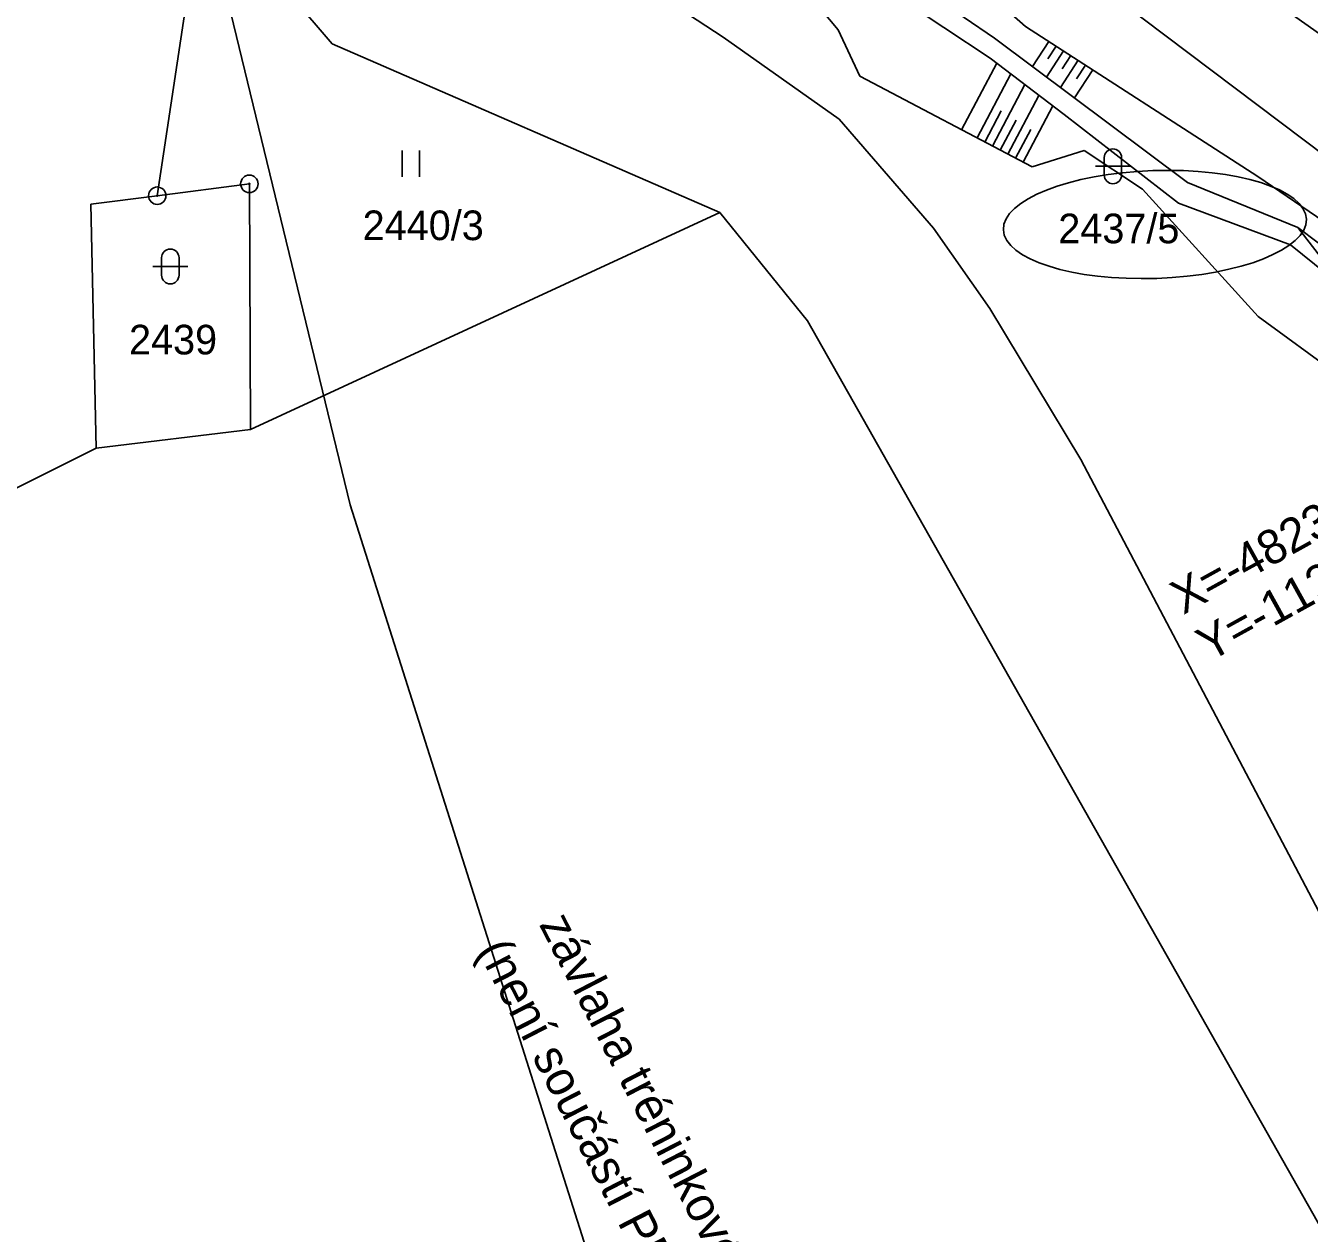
# Model space of a CAD drawing. Extents: x -483721 to -481876, y -1129170 to -1127366.
# Drawn here: x -482470.6 to -482396.9, y -1128316.3 to -1128247 of the extents above; entities that cross this region are included whole.
import ezdxf

# ---------------------------------------------------------------- set-up
doc = ezdxf.new("R2010")
doc.units = 0
for name, color, linetype in [('Hranice parcel', 7, 'Continuous'), ('kresba', 7, 'Continuous'), ('oblast', 7, 'Continuous'), ('Parcelní čísla', 7, 'Continuous'), ('SO 01', 7, 'Continuous'), ('u_návrh_popis', 7, 'Continuous'), ('u_OP_lesa', 7, 'Continuous'), ('u_vytyčení', 7, 'Continuous'), ('Značky bodu BP', 7, 'Continuous'), ('Značky kultur', 7, 'Continuous'), ('ˇ12', 7, 'Continuous')]:
    doc.layers.add(name, color=color, linetype=linetype)

msp = doc.modelspace()

# ---------------------------------------------------------------- linework, layer by layer
at = {"layer": 'Hranice parcel'}
for p, q in [((-482463, -1128256.76), (-482460.37, -1128239.37)), ((-482460.37, -1128239.37), (-482452.95, -1128248.05)), ((-482443.21, -1128239.32), (-482430.5, -1128247.66)), ((-482452.95, -1128248.05), (-482430.69, -1128257.73)), ((-482457.71, -1128256.08), (-482463, -1128256.76)), ((-482457.64, -1128270.17), (-482457.71, -1128256.08)), ((-482463, -1128256.76), (-482466.82, -1128257.25)), ((-482466.82, -1128257.25), (-482466.51, -1128271.25)), ((-482430.69, -1128257.73), (-482457.64, -1128270.17)), ((-482457.64, -1128270.17), (-482466.51, -1128271.25)), ((-482466.51, -1128271.25), (-482500.1, -1128287.99)), ((-482409.98, -1128271.91), (-482389.07, -1128311.59))]:
    msp.add_line(p, q, dxfattribs=at)
for points in [[(-482378.58, -1128267.55), (-482422.4, -1128234.54), (-482424.97, -1128232.6), (-482436.98, -1128222.89), (-482441.06, -1128219.38), (-482451.1, -1128211.21), (-482453.27, -1128206.98), (-482457.35, -1128200.28), (-482472.77, -1128174.94)], [(-482430.5, -1128247.66), (-482423.85, -1128252.37), (-482418.43, -1128258.62), (-482415.19, -1128263.23), (-482409.98, -1128271.91)], [(-482389.1, -1128328.49), (-482425.67, -1128263.94), (-482430.69, -1128257.73)]]:
    msp.add_lwpolyline(points, dxfattribs=at)
at = {"layer": 'kresba'}
msp.add_line((-482390.19, -1128268.135), (-482397.51, -1128258.578), dxfattribs=at)
at = {"layer": 'oblast'}
msp.add_ellipse((-482405.72, -1128258.412), major_axis=(-8.7, -0.304), ratio=0.355414, dxfattribs=at)
at = {"layer": 'SO 01'}
msp.add_lwpolyline([(-482368.023, -1128257.275), (-482390.756, -1128251.361), (-482390.756, -1128251.361), (-482399.122, -1128245.437)], dxfattribs=at)
at = {"layer": 'u_OP_lesa'}
msp.add_lwpolyline([(-482417.647, -1128382.401), (-482432.277, -1128336.352), (-482451.921, -1128274.508), (-482459.735, -1128242.317), (-482439.858, -1128216.048), (-482430.661, -1128194.677), (-482468.003, -1128132.413)], dxfattribs=at)
at = {"layer": 'Značky bodu BP'}
for centre, radius in [((-482457.71, -1128256.08), 0.5), ((-482463, -1128256.76), 0.5), ((-482457.71, -1128256.08), 0.0303), ((-482463, -1128256.76), 0.0303)]:
    msp.add_circle(centre, radius, dxfattribs=at)
at = {"layer": 'Značky kultur'}
for p, q in [((-482448.941, -1128255.67), (-482448.941, -1128254.17)), ((-482447.94, -1128255.67), (-482447.94, -1128254.17)), ((-482408.631, -1128254.571), (-482408.631, -1128255.572)), ((-482407.629, -1128255.572), (-482407.629, -1128254.571)), ((-482409.131, -1128255.071), (-482407.129, -1128255.071)), ((-482463.251, -1128260.821), (-482461.249, -1128260.821)), ((-482462.751, -1128260.321), (-482462.751, -1128261.322)), ((-482461.749, -1128261.322), (-482461.749, -1128260.321))]:
    msp.add_line(p, q, dxfattribs=at)
for centre, start, end in [((-482408.13, -1128254.571), 0, 180), ((-482408.13, -1128255.571), 180, 359.98789), ((-482462.25, -1128260.321), 0, 180), ((-482462.25, -1128261.321), 180, 359.98789)]:
    msp.add_arc(centre, 0.5, start, end, dxfattribs=at)
at = {"layer": 'ˇ12'}
for p, q in [((-482423.9, -1128247.24), (-482426.72, -1128243.88)), ((-482420.57, -1128243.86), (-482414.92, -1128247.72)), ((-482415.17, -1128248.87), (-482421.67, -1128244.55)), ((-482416.51, -1128244.08), (-482413.14, -1128247.04)), ((-482422.66, -1128249.89), (-482423.9, -1128247.24)), ((-482413.14, -1128247.04), (-482399.8, -1128255.66)), ((-482414.92, -1128247.72), (-482403.85, -1128256)), ((-482411.8, -1128247.9), (-482412.74, -1128249.35)), ((-482411.38, -1128248.17), (-482411.86, -1128248.91)), ((-482416.82, -1128252.97), (-482414.8, -1128249.15)), ((-482415.17, -1128248.87), (-482410.93, -1128252.1)), ((-482410.96, -1128248.45), (-482411.94, -1128249.95)), ((-482410.12, -1128248.99), (-482411.13, -1128250.55)), ((-482410.54, -1128248.72), (-482411.04, -1128249.48)), ((-482412.76, -1128255.11), (-482422.66, -1128249.89)), ((-482415.93, -1128253.44), (-482413.99, -1128249.77)), ((-482409.28, -1128249.53), (-482410.33, -1128251.15)), ((-482409.7, -1128249.26), (-482410.22, -1128250.06)), ((-482415.04, -1128253.91), (-482413.18, -1128250.38)), ((-482414.16, -1128254.38), (-482412.38, -1128251)), ((-482415.49, -1128253.68), (-482414.54, -1128251.88)), ((-482413.28, -1128254.84), (-482411.57, -1128251.61)), ((-482410.93, -1128252.1), (-482404.37, -1128257.19)), ((-482414.6, -1128254.14), (-482413.69, -1128252.42)), ((-482413.72, -1128254.61), (-482412.85, -1128252.96)), ((-482409.78, -1128254.16), (-482412.76, -1128255.11)), ((-482409.78, -1128254.16), (-482406.43, -1128256.39)), ((-482399.8, -1128255.66), (-482389.79, -1128262.5)), ((-482406.43, -1128256.39), (-482399.79, -1128263.7)), ((-482403.85, -1128256), (-482397.51, -1128258.58)), ((-482404.37, -1128257.19), (-482397.94, -1128259.58)), ((-482397.51, -1128258.58), (-482394.31, -1128261.02)), ((-482397.94, -1128259.58), (-482394.62, -1128262.26)), ((-482399.79, -1128263.7), (-482394.21, -1128267.77))]:
    msp.add_line(p, q, dxfattribs=at)

# ---------------------------------------------------------------- texts
at = {"layer": 'Parcelní čísla'}
for s, p in [('2440/3', (-482451.205, -1128259.31)), ('2437/5', (-482411.265, -1128259.49)), ('2439', (-482464.62, -1128265.87))]:
    msp.add_text(s, height=1.7, dxfattribs=at).set_placement(p)
at = {"layer": 'u_návrh_popis'}
for s, p in [('závlaha tréninkového fotbalového hřiště - 7 350 m2', (-482441.103, -1128298.576)), ('(není součástí PD)', (-482444.645, -1128300.07))]:
    msp.add_text(s, height=2, rotation=297.29917, dxfattribs=at).set_placement(p)
at = {"layer": 'u_vytyčení'}
for s, p in [('X=-482385.8778', (-482404.092, -1128280.836)), ('Y=-1128270.1536', (-482402.594, -1128283.543))]:
    msp.add_text(s, height=1.96875, rotation=28.95592, dxfattribs=at).set_placement(p)

doc.saveas('drawing.dxf')
